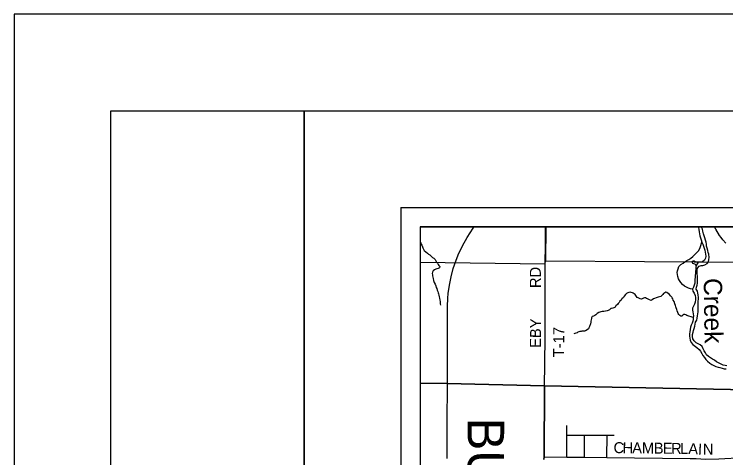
# Model space of a CAD drawing. Extents: x -7.3 to 34, y 0 to 22.
# Drawn here: x 0 to 3.68, y 19.706 to 22 of the extents above; entities that cross this region are included whole.
import ezdxf

# ---------------------------------------------------------------- set-up
doc = ezdxf.new("R2010")
doc.units = 0
for name, color, linetype in [('GM_X_Corporation', 7, 'Continuous'), ('GM_X_County_Text', 7, 'Continuous'), ('GM_X_Major_River', 7, 'Continuous'), ('GM_X_Major_River_Text', 7, 'Continuous'), ('GM_X_Minor_River', 7, 'Continuous'), ('GM_X_State_Location', 7, 'Continuous'), ('GM_X_State_Route', 7, 'Continuous'), ('GM_X_Township_Road', 7, 'Continuous'), ('GM_X_Township_Road_Text', 7, 'Continuous'), ('SH_Border', 7, 'Continuous'), ('SH_Cut_Line', 7, 'Continuous'), ('SH_Data', 7, 'Continuous')]:
    doc.layers.add(name, color=color, linetype=linetype)

msp = doc.modelspace()

# ---------------------------------------------------------------- linework, layer by layer
at = {"layer": 'GM_X_Corporation'}
for points in [[(8.9, 20.9), (2.1, 20.9), (2.1, 20.0921), (2.24, 20.0891), (2.7422, 20.0783), (4.2288, 20.048)], [(2.7401, 19.6966), (2.7402, 19.7107), (2.7422, 20.0783), (2.24, 20.0891), (2.1, 20.0921), (2.1, 14.1)], [(2.7401, 19.6966), (2.7402, 19.7107), (2.7422, 20.0783), (2.24, 20.0891), (2.1, 20.0921), (2.1, 17.0429)], [(4.2288, 20.048), (2.7422, 20.0783), (2.7402, 19.7107), (2.7401, 19.6966)], [(4.2288, 20.048), (2.7422, 20.0783), (2.7402, 19.7107), (2.7401, 19.6966)]]:
    msp.add_lwpolyline(points, dxfattribs=at)
for points in [[(2.7489, 20.9), (2.1, 20.9), (2.1, 20.7169), (2.7467, 20.7086), (2.7471, 20.7249)], [(4.7796, 20.9), (2.1, 20.9), (2.1, 20.0921), (2.24, 20.0891), (2.7422, 20.0783), (4.2288, 20.048), (4.2328, 20.0479), (4.4762, 20.0428), (4.7954, 20.036), (4.7977, 20.2101), (4.804, 20.71), (4.7927, 20.7114), (4.7847, 20.7149), (4.7798, 20.7211), (4.7788, 20.7252), (4.7788, 20.7319), (4.7799, 20.7827)], [(3.7726, 20.9), (2.7489, 20.9), (2.7471, 20.7249), (3.7718, 20.7175)]]:
    msp.add_lwpolyline(points, close=True, dxfattribs=at)
at = {"layer": 'GM_X_Major_River'}
msp.add_line((3.5282, 20.6997), (3.5388, 20.7168), dxfattribs=at)
for points in [[(3.6867, 20.182), (3.6764, 20.1833), (3.6666, 20.1846), (3.6564, 20.189), (3.6429, 20.1961), (3.6324, 20.2027), (3.6219, 20.2101), (3.6117, 20.2156), (3.6012, 20.2234), (3.5907, 20.2289), (3.581, 20.2382), (3.5747, 20.2482), (3.5681, 20.2586), (3.5634, 20.2697), (3.5575, 20.2808), (3.5474, 20.2897), (3.5376, 20.2948), (3.5271, 20.2996), (3.5163, 20.3108), (3.5108, 20.3215), (3.508, 20.3333), (3.5089, 20.344), (3.511, 20.3546), (3.5131, 20.3644), (3.5167, 20.3746), (3.5204, 20.3871), (3.5246, 20.4067), (3.5305, 20.4176), (3.5322, 20.4282), (3.5343, 20.4396), (3.536, 20.4502), (3.537, 20.4604), (3.5376, 20.4707), (3.5374, 20.4817), (3.538, 20.4916), (3.5378, 20.5037), (3.538, 20.5151), (3.539, 20.5257), (3.5395, 20.5352), (3.5383, 20.5478), (3.5366, 20.5573), (3.5333, 20.5672), (3.5275, 20.5783), (3.5284, 20.5878), (3.5324, 20.5991), (3.5337, 20.6094), (3.5347, 20.6211), (3.5342, 20.6337), (3.5337, 20.6458), (3.5331, 20.6553), (3.5325, 20.6656), (3.5327, 20.6766), (3.5341, 20.6865), (3.5423, 20.6973), (3.5526, 20.7002), (3.5621, 20.7008), (3.572, 20.7029), (3.5835, 20.7099), (3.5905, 20.7196), (3.5934, 20.731), (3.5951, 20.7423), (3.592, 20.7587), (3.5892, 20.7683), (3.5871, 20.7785), (3.5839, 20.79), (3.5807, 20.7999), (3.5805, 20.8106), (3.5795, 20.8208), (3.5759, 20.8312), (3.5712, 20.843), (3.568, 20.8533), (3.5648, 20.8644), (3.5616, 20.877), (3.5595, 20.8877), (3.5541, 20.8984), (3.5534, 20.9)], [(3.5387, 20.9), (3.5392, 20.8964), (3.5402, 20.8869), (3.5422, 20.8747), (3.5439, 20.8644), (3.546, 20.8545), (3.5496, 20.8434), (3.5524, 20.8331), (3.5571, 20.8212), (3.5615, 20.8113), (3.5659, 20.7998), (3.5691, 20.7899), (3.5719, 20.7788), (3.5736, 20.7693), (3.5757, 20.7594), (3.5767, 20.7484), (3.5757, 20.7389), (3.5702, 20.7283), (3.5601, 20.719), (3.5506, 20.7173), (3.5411, 20.7167), (3.5388, 20.7168)], [(3.5388, 20.7168), (3.5278, 20.7173), (3.5222, 20.7197), (3.5165, 20.7225), (3.5112, 20.7229), (3.5073, 20.7192), (3.5069, 20.7158), (3.5084, 20.7124), (3.5133, 20.7104), (3.5178, 20.7088), (3.5216, 20.7076), (3.5245, 20.7037), (3.5282, 20.6997)], [(3.5282, 20.6997), (3.5258, 20.6931), (3.5249, 20.6813), (3.5243, 20.6707), (3.5233, 20.6604), (3.5224, 20.651), (3.5214, 20.6404), (3.5201, 20.6286), (3.5203, 20.6191), (3.5197, 20.6081), (3.5172, 20.5983), (3.5128, 20.5885), (3.5081, 20.5779), (3.5094, 20.5673), (3.5175, 20.5565), (3.5219, 20.5458), (3.5232, 20.5351), (3.523, 20.5245), (3.5216, 20.5112), (3.5191, 20.5003), (3.5129, 20.4901), (3.5085, 20.4803), (3.5087, 20.4697), (3.5104, 20.4598), (3.5121, 20.4495), (3.5127, 20.44), (3.5125, 20.4305), (3.5115, 20.421), (3.5102, 20.4115), (3.5066, 20.4014), (3.5019, 20.3916), (3.4983, 20.381), (3.4958, 20.3693), (3.494, 20.3568), (3.4934, 20.3469), (3.4932, 20.3355), (3.4945, 20.3245), (3.497, 20.3134), (3.5013, 20.3012), (3.5098, 20.2908), (3.5312, 20.276), (3.5424, 20.2663), (3.5502, 20.2566), (3.5572, 20.2447), (3.5623, 20.2351), (3.5701, 20.2251), (3.5771, 20.2144), (3.5864, 20.2047), (3.5976, 20.1946), (3.6078, 20.188), (3.6194, 20.1824), (3.6292, 20.1781), (3.6402, 20.1749), (3.65, 20.1724), (3.6613, 20.1688), (3.6712, 20.1663), (3.6822, 20.165)]]:
    msp.add_lwpolyline(points, dxfattribs=at)
at = {"layer": 'GM_X_Minor_River'}
for points in [[(2.3176, 20.9), (2.319, 20.8995), (2.3239, 20.8994), (2.3268, 20.9)], [(2.1, 20.8241), (2.1013, 20.8213), (2.1056, 20.8113), (2.1081, 20.8052), (2.1109, 20.7968), (2.1134, 20.791), (2.1162, 20.7852), (2.1206, 20.7783), (2.1295, 20.7701), (2.1373, 20.7638), (2.1432, 20.7591), (2.1495, 20.7548), (2.1562, 20.7493), (2.1643, 20.7419), (2.1707, 20.7375), (2.1765, 20.7305), (2.1809, 20.7244), (2.1849, 20.7178), (2.1885, 20.712), (2.1925, 20.7062), (2.1969, 20.7), (2.2009, 20.6942), (2.2, 20.6882), (2.1923, 20.6842), (2.1866, 20.6825), (2.1808, 20.6811), (2.1735, 20.6771), (2.1677, 20.6724), (2.1637, 20.6653), (2.1624, 20.6589), (2.163, 20.6524), (2.1643, 20.6463), (2.1649, 20.6398), (2.167, 20.6329), (2.169, 20.6234), (2.1728, 20.6119), (2.1768, 20.6035), (2.18, 20.5951), (2.1832, 20.587), (2.1852, 20.5805), (2.1877, 20.5732), (2.1905, 20.5663), (2.193, 20.5594), (2.1947, 20.5529), (2.196, 20.5461), (2.1981, 20.5384), (2.1994, 20.5308), (2.201, 20.5202), (2.2024, 20.514), (2.203, 20.5083), (2.2039, 20.5015), (2.2045, 20.4954)], [(3.5081, 20.5779), (3.4982, 20.5792), (3.4869, 20.5836), (3.4771, 20.5876), (3.4662, 20.5931), (3.4557, 20.602), (3.4483, 20.6121), (3.4409, 20.6224), (3.4366, 20.632), (3.4322, 20.6435), (3.4301, 20.6538), (3.4296, 20.6633), (3.4309, 20.6731), (3.4337, 20.683), (3.4381, 20.6943), (3.4478, 20.7047), (3.4594, 20.7129), (3.4694, 20.7191), (3.4797, 20.7258), (3.4901, 20.7321), (3.4997, 20.7387), (3.5094, 20.7473), (3.5194, 20.7562), (3.5295, 20.7659), (3.5396, 20.7767), (3.5455, 20.7877), (3.5495, 20.7978), (3.5571, 20.8212)], [(3.5125, 20.4305), (3.4796, 20.4418), (3.4743, 20.445), (3.4679, 20.4463), (3.4629, 20.4464), (3.4579, 20.4439), (3.4524, 20.4384), (3.4474, 20.4382), (3.4422, 20.4413), (3.437, 20.4461), (3.4341, 20.4518), (3.4327, 20.4568), (3.4296, 20.4664), (3.4267, 20.4733), (3.4243, 20.481), (3.4222, 20.4867), (3.4208, 20.4925), (3.4173, 20.5024), (3.4127, 20.514), (3.4087, 20.5209), (3.4066, 20.527), (3.4029, 20.5321), (3.4007, 20.5367), (3.3949, 20.5441), (3.3885, 20.5496), (3.3822, 20.5555), (3.3763, 20.5598), (3.371, 20.5619), (3.3644, 20.5586), (3.3589, 20.5546), (3.355, 20.5494), (3.3495, 20.5443), (3.344, 20.5399), (3.3371, 20.5382), (3.3305, 20.5361), (3.3248, 20.5348), (3.3201, 20.5326), (3.3116, 20.5295), (3.3066, 20.5273), (3.3004, 20.5218), (3.2946, 20.5197), (3.2863, 20.5222), (3.275, 20.5271), (3.2701, 20.5299), (3.2652, 20.5323), (3.2595, 20.5321), (3.2545, 20.5304), (3.2487, 20.5283), (3.2437, 20.5269), (3.2383, 20.5274), (3.2278, 20.5323), (3.2222, 20.5348), (3.2189, 20.5402), (3.2156, 20.5448), (3.2119, 20.5499), (3.2067, 20.5542), (3.2022, 20.5577), (3.1973, 20.5594), (3.1909, 20.5611), (3.1856, 20.5616), (3.1787, 20.5603), (3.1733, 20.5586), (3.1671, 20.555), (3.1623, 20.5502), (3.1548, 20.5421), (3.1512, 20.5346), (3.143, 20.5272), (3.1394, 20.5216), (3.1331, 20.515), (3.1298, 20.509), (3.1232, 20.5039), (3.1204, 20.4983), (3.1121, 20.4909), (3.1074, 20.485), (3.1011, 20.481), (3.0954, 20.4789), (3.0896, 20.4779), (3.085, 20.4777), (3.0795, 20.471), (3.0725, 20.4674), (3.0671, 20.4657), (3.0583, 20.4641), (3.0491, 20.4628), (3.0403, 20.4615), (3.0345, 20.4598), (3.0295, 20.4584), (3.0241, 20.4563), (3.016, 20.4516), (3.0089, 20.4458), (3.0023, 20.4407), (2.9961, 20.4378), (2.9892, 20.4365), (2.9856, 20.4298), (2.985, 20.4252), (2.9841, 20.4184), (2.9831, 20.412), (2.9818, 20.4075), (2.9801, 20.3992), (2.9747, 20.3845), (2.9726, 20.3785), (2.9701, 20.3721)], [(2.9701, 20.3721), (2.9639, 20.367), (2.9553, 20.3627), (2.9503, 20.3613), (2.9438, 20.3604), (2.9366, 20.3598), (2.9316, 20.3592), (2.9251, 20.3587), (2.9158, 20.3548), (2.9112, 20.3526), (2.9042, 20.3509), (2.8988, 20.3481), (2.8938, 20.3467)]]:
    msp.add_lwpolyline(points, dxfattribs=at)
at = {"layer": 'GM_X_State_Route'}
for points in [[(2.2402, 20.0886), (2.241, 20.4883), (2.2429, 20.5314), (2.2453, 20.5558), (2.2512, 20.5983), (2.2599, 20.6422), (2.2711, 20.6841), (2.2843, 20.7231), (2.297, 20.7558), (2.3189, 20.8026), (2.3426, 20.8453), (2.373, 20.8932), (2.3783, 20.9)], [(3.6812, 20.8161), (3.6656, 20.8323), (3.6557, 20.8444), (3.6472, 20.8562), (3.6286, 20.8879), (3.6221, 20.9)], [(2.2391, 19.7025), (2.2394, 19.7842), (2.2396, 19.8672), (2.24, 19.9473), (2.2404, 20.0258), (2.2402, 20.0886)]]:
    msp.add_lwpolyline(points, dxfattribs=at)
at = {"layer": 'GM_X_Township_Road'}
for p, q in [((2.7404, 19.7101), (2.7424, 20.0778)), ((2.9475, 19.8227), (2.9479, 19.708)), ((3.0647, 19.7067), (3.067, 19.8228)), ((2.7404, 19.6961), (2.7404, 19.7101))]:
    msp.add_line(p, q, dxfattribs=at)
for points in [[(2.7424, 20.0778), (2.7443, 20.1892), (2.7457, 20.3323), (2.7467, 20.4553), (2.7459, 20.5605), (2.7458, 20.6854), (2.7473, 20.8315), (2.7482, 20.9)], [(2.858, 19.7089), (2.8577, 19.8226), (2.8576, 19.8732)], [(2.8577, 19.8226), (2.9475, 19.8227), (3.067, 19.8228), (3.1035, 19.8228)], [(2.7404, 19.7101), (2.858, 19.7089), (2.9479, 19.708), (3.0647, 19.7067), (3.496, 19.7022), (3.5279, 19.7011), (3.5753, 19.6985), (3.6451, 19.6996), (3.7699, 19.707), (3.8048, 19.7068)]]:
    msp.add_lwpolyline(points, dxfattribs=at)
at = {"layer": 'SH_Border'}
for points in [[(0.5, 21.5), (1.5, 21.5), (1.5, 0.5), (0.5, 0.5)], [(1.5, 21.5), (33.5, 21.5), (33.5, 0.5), (1.5, 0.5)]]:
    msp.add_lwpolyline(points, close=True, dxfattribs=at)
at = {"layer": 'SH_Cut_Line'}
msp.add_lwpolyline([(0, 0), (34, 0), (34, 22), (0, 22)], close=True, dxfattribs=at)
at = {"layer": 'SH_Data'}
for p, q in [((2, 21), (9, 21)), ((2, 21), (2, 14)), ((2.1, 20.9), (2.1, 14.1)), ((2.1, 20.9), (8.9, 20.9))]:
    msp.add_line(p, q, dxfattribs=at)

# ---------------------------------------------------------------- texts
at = {"layer": 'GM_X_County_Text'}
msp.add_text('BUTLER COUNTY', height=0.189394, rotation=269.9014, dxfattribs=at).set_placement((2.3449, 19.913))
at = {"layer": 'GM_X_Major_River_Text'}
msp.add_text('Creek', height=0.09467, rotation=270.84, dxfattribs=at).set_placement((3.5661, 20.6343))
at = {"layer": 'GM_X_State_Location'}
for s in ['s', 'r']:
    msp.add_text(s, height=0.000189, dxfattribs=at).set_placement((3.6265, 20.8701))
msp.add_text('123', height=0.000189, rotation=0, dxfattribs=at).set_placement((3.5596, 20.8563))
at = {"layer": 'GM_X_Township_Road_Text'}
for s, height, rotation, p in [('RD', 0.05682, 90, (2.7238, 20.5835)), ('EBY', 0.05682, 89.3142, (2.7238, 20.2738)), ('T-17', 0.05682, 89.6465, (2.8441, 20.2254)), ('C', 0.0568, 359.274, (3.0995, 19.7299)), ('H', 0.0568, 359.2774, (3.1462, 19.7293)), ('A', 0.0568, 359.2787, (3.1962, 19.7287)), ('M', 0.0568, 359.2734, (3.2461, 19.7281)), ('B', 0.0568, 359.2788, (3.3078, 19.7273)), ('E', 0.0568, 359.2714, (3.3545, 19.7267)), ('R', 0.0568, 359.2788, (3.397, 19.7261)), ('L', 0.0568, 359.0143, (3.4436, 19.7256)), ('A', 0.0568, 357.6972, (3.4857, 19.7248)), ('I', 0.0568, 357.1731, (3.5355, 19.7228)), ('N', 0.0568, 359.8686, (3.5618, 19.7216))]:
    msp.add_text(s, height=height, rotation=rotation, dxfattribs=at).set_placement(p)

doc.saveas('drawing.dxf')
